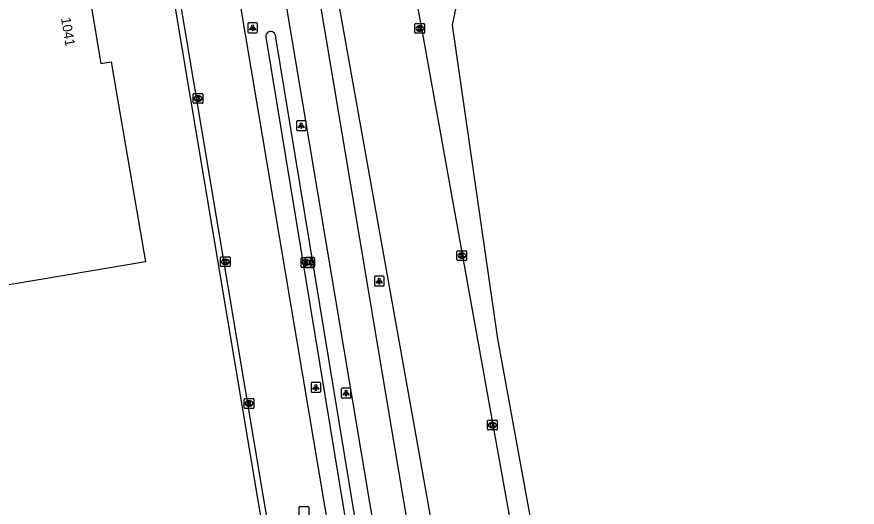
# Model space of a CAD drawing. Extents: x 154324 to 155743, y 382939 to 384183.
# Drawn here: x 155014.9 to 155101.4, y 383566.8 to 383617.3 of the extents above; entities that cross this region are included whole.
import ezdxf

# ---------------------------------------------------------------- set-up
doc = ezdxf.new("R2010")
doc.units = 0
for name, color, linetype in [('IMGEO_Brandkraan', 7, 'Continuous'), ('IMGEO_Fietspad_gesloten', 7, 'Continuous'), ('IMGEO_Greppel_droge_sloot', 7, 'Continuous'), ('IMGEO_Kolk', 7, 'Continuous'), ('IMGEO_Lichtpunt', 7, 'Continuous'), ('IMGEO_Loofbos', 7, 'Continuous'), ('IMGEO_Pand', 7, 'Continuous'), ('IMGEO_Pand_nummerreeks', 7, 'Continuous'), ('IMGEO_Rijbaan_lokaal_gesloten', 7, 'Continuous'), ('IMGEO_Rijbaan_lokaal_open', 7, 'Continuous'), ('IMGEO_Rijbaan_regionaal_gesloten', 7, 'Continuous'), ('IMGEO_Rioolput', 7, 'Continuous'), ('IMGEO_Verklikker', 7, 'Continuous')]:
    doc.layers.add(name, color=color, linetype=linetype)

msp = doc.modelspace()

# ---------------------------------------------------------------- linework, layer by layer
at = {"layer": 'IMGEO_Brandkraan'}
for p, q in [((155044.137, 383591.543), (155044.137, 383592.395)), ((155044.212, 383592.469), (155045.064, 383592.469)), ((155044.625, 383592.249), (155044.65, 383592.249)), ((155045.138, 383592.395), (155045.138, 383591.543)), ((155045.064, 383591.469), (155044.212, 383591.469)), ((155044.648, 383591.689), (155044.623, 383591.689))]:
    msp.add_line(p, q, dxfattribs=at)
for points in [[(155044.137, 383591.543), (155044.137, 383592.395)], [(155044.212, 383592.469), (155045.064, 383592.469)], [(155044.485, 383592.169), (155044.485, 383591.769), (155044.698, 383591.769)], [(155044.716, 383592.169), (155044.485, 383592.169)], [(155044.664, 383592.088), (155044.61, 383592.088), (155044.61, 383592.012)], [(155044.61, 383592.012), (155044.663, 383592.012)], [(155044.672, 383591.936), (155044.61, 383591.936), (155044.61, 383591.855)], [(155044.61, 383591.855), (155044.672, 383591.855)], [(155045.138, 383592.395), (155045.138, 383591.543)], [(155045.064, 383591.469), (155044.212, 383591.469)]]:
    msp.add_lwpolyline(points, dxfattribs=at)
for centre, radius, start, end in [((155044.214, 383592.393), 0.0765, 91.55205, 178.44795), ((155044.214, 383592.393), 0.0765, 91.55205, 178.44795), ((155044.665, 383592.05), 0.0379, 267.82845, 90.93552), ((155044.673, 383591.895), 0.0404, 269.87594, 90.50774), ((155044.704, 383592.02), 0.251, 268.66757, 293.53466), ((155044.72, 383592.024), 0.145, 59.4692, 91.53667), ((155044.745, 383592.071), 0.0922, 285.51372, 58.15012), ((155044.75, 383591.879), 0.105, 301.31148, 78.98903), ((155045.062, 383592.393), 0.0765, 1.55205, 88.44795), ((155045.062, 383592.393), 0.0765, 1.55205, 88.44795), ((155044.214, 383591.545), 0.0765, 181.55205, 268.44795), ((155044.214, 383591.545), 0.0765, 181.55205, 268.44795), ((155045.062, 383591.545), 0.0765, 271.55205, 358.44795), ((155045.062, 383591.545), 0.0765, 271.55205, 358.44795)]:
    msp.add_arc(centre, radius, start, end, dxfattribs=at)
for centre, major_axis, ratio, start_param, end_param in [((155044.624, 383591.969), (-0.387, 0.002), 0.722429, 4.712389, 7.853982), ((155044.649, 383591.969), (-0.39, 0.002), 0.717154, 1.570796, 4.712389)]:
    msp.add_ellipse(centre, major_axis=major_axis, ratio=ratio, start_param=start_param, end_param=end_param, dxfattribs=at)
at = {"layer": 'IMGEO_Fietspad_gesloten'}
for points in [[(155069.375, 383489.212), (155067.803, 383490.288), (155064.93, 383506.848), (155055.586, 383562.322), (155035.787, 383680.446), (155030.556, 383711.937), (155024.582, 383747.491), (155023.65, 383752.887)], [(155020.155, 383752.117), (155027.003, 383711.594), (155027.513, 383708.543), (155029.197, 383698.769), (155030.596, 383690.066), (155052.123, 383561.719), (155057.1, 383532.805), (155064.796, 383488.095)]]:
    msp.add_lwpolyline(points, dxfattribs=at)
at = {"layer": 'IMGEO_Greppel_droge_sloot'}
for points in [[(155040.514, 383615.174), (155060.78, 383492.297)], [(155061.766, 383492.46), (155041.5, 383615.337)]]:
    msp.add_lwpolyline(points, dxfattribs=at)
msp.add_arc((155041.007, 383615.256), 0.5, 9.30266, 189.47118, dxfattribs=at)
at = {"layer": 'IMGEO_Kolk'}
for p, q in [((155055.864, 383615.653), (155055.864, 383616.505)), ((155055.939, 383616.579), (155056.791, 383616.579)), ((155056.352, 383616.359), (155056.377, 383616.359)), ((155056.865, 383616.505), (155056.865, 383615.653)), ((155056.791, 383615.579), (155055.939, 383615.579)), ((155056.375, 383615.799), (155056.35, 383615.799)), ((155033.026, 383608.442), (155033.026, 383609.294)), ((155033.101, 383609.368), (155033.953, 383609.368)), ((155033.514, 383609.148), (155033.539, 383609.148)), ((155034.027, 383609.294), (155034.027, 383608.442)), ((155033.953, 383608.368), (155033.101, 383608.368)), ((155033.537, 383608.588), (155033.512, 383608.588)), ((155060.19, 383592.251), (155060.19, 383593.103)), ((155060.265, 383593.177), (155061.117, 383593.177)), ((155060.678, 383592.957), (155060.703, 383592.957)), ((155061.191, 383593.103), (155061.191, 383592.251)), ((155035.847, 383591.622), (155035.847, 383592.474)), ((155035.922, 383592.548), (155036.774, 383592.548)), ((155036.358, 383591.768), (155036.333, 383591.768)), ((155036.335, 383592.328), (155036.36, 383592.328)), ((155036.848, 383592.474), (155036.848, 383591.622)), ((155061.117, 383592.177), (155060.265, 383592.177)), ((155060.701, 383592.397), (155060.676, 383592.397)), ((155036.774, 383591.548), (155035.922, 383591.548)), ((155038.282, 383577.025), (155038.282, 383577.877)), ((155038.357, 383577.951), (155039.209, 383577.951)), ((155039.283, 383577.877), (155039.283, 383577.025)), ((155038.793, 383577.171), (155038.768, 383577.171)), ((155038.77, 383577.731), (155038.795, 383577.731)), ((155039.209, 383576.951), (155038.357, 383576.951)), ((155063.341, 383574.803), (155063.341, 383575.655)), ((155063.416, 383575.729), (155064.268, 383575.729)), ((155063.829, 383575.509), (155063.854, 383575.509)), ((155064.342, 383575.655), (155064.342, 383574.803)), ((155064.268, 383574.729), (155063.416, 383574.729)), ((155063.852, 383574.949), (155063.827, 383574.949))]:
    msp.add_line(p, q, dxfattribs=at)
for points in [[(155055.864, 383615.653), (155055.864, 383616.505)], [(155055.939, 383616.579), (155056.791, 383616.579)], [(155056.185, 383616.279), (155056.308, 383616.279), (155056.308, 383616.128), (155056.438, 383616.279), (155056.602, 383616.279), (155056.456, 383616.128), (155056.609, 383615.879), (155056.457, 383615.879), (155056.372, 383616.043), (155056.308, 383615.976), (155056.308, 383615.879), (155056.185, 383615.879), (155056.185, 383616.279)], [(155056.865, 383616.505), (155056.865, 383615.653)], [(155056.791, 383615.579), (155055.939, 383615.579)], [(155033.026, 383608.442), (155033.026, 383609.294)], [(155033.101, 383609.368), (155033.953, 383609.368)], [(155033.347, 383609.068), (155033.47, 383609.068), (155033.47, 383608.917), (155033.6, 383609.068), (155033.764, 383609.068), (155033.618, 383608.917), (155033.771, 383608.668), (155033.619, 383608.668), (155033.534, 383608.832), (155033.47, 383608.765), (155033.47, 383608.668), (155033.347, 383608.668), (155033.347, 383609.068)], [(155034.027, 383609.294), (155034.027, 383608.442)], [(155033.953, 383608.368), (155033.101, 383608.368)], [(155060.19, 383592.251), (155060.19, 383593.103)], [(155060.265, 383593.177), (155061.117, 383593.177)], [(155060.511, 383592.877), (155060.634, 383592.877), (155060.634, 383592.726), (155060.764, 383592.877), (155060.928, 383592.877), (155060.782, 383592.726), (155060.935, 383592.477), (155060.783, 383592.477), (155060.698, 383592.641), (155060.634, 383592.574), (155060.634, 383592.477), (155060.511, 383592.477), (155060.511, 383592.877)], [(155061.191, 383593.103), (155061.191, 383592.251)], [(155035.847, 383591.622), (155035.847, 383592.474)], [(155035.922, 383592.548), (155036.774, 383592.548)], [(155036.168, 383592.248), (155036.291, 383592.248), (155036.291, 383592.097), (155036.421, 383592.248), (155036.585, 383592.248), (155036.439, 383592.097), (155036.592, 383591.848), (155036.44, 383591.848), (155036.355, 383592.012), (155036.291, 383591.945), (155036.291, 383591.848), (155036.168, 383591.848), (155036.168, 383592.248)], [(155036.848, 383592.474), (155036.848, 383591.622)], [(155061.117, 383592.177), (155060.265, 383592.177)], [(155036.774, 383591.548), (155035.922, 383591.548)], [(155038.282, 383577.025), (155038.282, 383577.877)], [(155038.357, 383577.951), (155039.209, 383577.951)], [(155039.283, 383577.877), (155039.283, 383577.025)], [(155038.603, 383577.651), (155038.726, 383577.651), (155038.726, 383577.5), (155038.856, 383577.651), (155039.02, 383577.651), (155038.874, 383577.5), (155039.027, 383577.251), (155038.875, 383577.251), (155038.79, 383577.415), (155038.726, 383577.348), (155038.726, 383577.251), (155038.603, 383577.251), (155038.603, 383577.651)], [(155039.209, 383576.951), (155038.357, 383576.951)], [(155063.341, 383574.803), (155063.341, 383575.655)], [(155063.416, 383575.729), (155064.268, 383575.729)], [(155063.662, 383575.429), (155063.785, 383575.429), (155063.785, 383575.278), (155063.915, 383575.429), (155064.079, 383575.429), (155063.933, 383575.278), (155064.086, 383575.029), (155063.934, 383575.029), (155063.849, 383575.193), (155063.785, 383575.126), (155063.785, 383575.029), (155063.662, 383575.029), (155063.662, 383575.429)], [(155064.342, 383575.655), (155064.342, 383574.803)], [(155064.268, 383574.729), (155063.416, 383574.729)]]:
    msp.add_lwpolyline(points, dxfattribs=at)
for centre, start, end in [((155055.941, 383616.503), 91.55205, 178.44795), ((155055.941, 383616.503), 91.55205, 178.44795), ((155056.789, 383616.503), 1.55205, 88.44795), ((155056.789, 383616.503), 1.55205, 88.44795), ((155055.941, 383615.655), 181.55205, 268.44795), ((155055.941, 383615.655), 181.55205, 268.44795), ((155056.789, 383615.655), 271.55205, 358.44795), ((155056.789, 383615.655), 271.55205, 358.44795), ((155033.103, 383609.292), 91.55205, 178.44795), ((155033.103, 383609.292), 91.55205, 178.44795), ((155033.951, 383609.292), 1.55205, 88.44795), ((155033.951, 383609.292), 1.55205, 88.44795), ((155033.103, 383608.444), 181.55205, 268.44795), ((155033.103, 383608.444), 181.55205, 268.44795), ((155033.951, 383608.444), 271.55205, 358.44795), ((155033.951, 383608.444), 271.55205, 358.44795), ((155060.267, 383593.101), 91.55205, 178.44795), ((155060.267, 383593.101), 91.55205, 178.44795), ((155061.115, 383593.101), 1.55205, 88.44795), ((155061.115, 383593.101), 1.55205, 88.44795), ((155035.924, 383592.472), 91.55205, 178.44795), ((155035.924, 383592.472), 91.55205, 178.44795), ((155036.772, 383592.472), 1.55205, 88.44795), ((155036.772, 383592.472), 1.55205, 88.44795), ((155060.267, 383592.253), 181.55205, 268.44795), ((155060.267, 383592.253), 181.55205, 268.44795), ((155061.115, 383592.253), 271.55205, 358.44795), ((155061.115, 383592.253), 271.55205, 358.44795), ((155035.924, 383591.624), 181.55205, 268.44795), ((155035.924, 383591.624), 181.55205, 268.44795), ((155036.772, 383591.624), 271.55205, 358.44795), ((155036.772, 383591.624), 271.55205, 358.44795), ((155038.359, 383577.875), 91.55205, 178.44795), ((155038.359, 383577.875), 91.55205, 178.44795), ((155039.207, 383577.875), 1.55205, 88.44795), ((155039.207, 383577.875), 1.55205, 88.44795), ((155038.359, 383577.027), 181.55205, 268.44795), ((155038.359, 383577.027), 181.55205, 268.44795), ((155039.207, 383577.027), 271.55205, 358.44795), ((155039.207, 383577.027), 271.55205, 358.44795), ((155063.418, 383575.653), 91.55205, 178.44795), ((155063.418, 383575.653), 91.55205, 178.44795), ((155064.266, 383575.653), 1.55205, 88.44795), ((155064.266, 383575.653), 1.55205, 88.44795), ((155063.418, 383574.805), 181.55205, 268.44795), ((155063.418, 383574.805), 181.55205, 268.44795), ((155064.266, 383574.805), 271.55205, 358.44795), ((155064.266, 383574.805), 271.55205, 358.44795)]:
    msp.add_arc(centre, 0.0765, start, end, dxfattribs=at)
for centre, major_axis, ratio, start_param, end_param in [((155056.351, 383616.079), (-0.387, 0.002), 0.722429, 4.712389, 7.853982), ((155056.376, 383616.079), (-0.39, 0.002), 0.717154, 1.570796, 4.712389), ((155033.513, 383608.868), (-0.387, 0.002), 0.722429, 4.712389, 7.853982), ((155033.538, 383608.868), (-0.39, 0.002), 0.717154, 1.570796, 4.712389), ((155060.677, 383592.677), (-0.387, 0.002), 0.722429, 4.712389, 7.853982), ((155060.702, 383592.677), (-0.39, 0.002), 0.717154, 1.570796, 4.712389), ((155036.334, 383592.048), (-0.387, 0.002), 0.722429, 4.712389, 7.853982), ((155036.359, 383592.048), (-0.39, 0.002), 0.717154, 1.570796, 4.712389), ((155038.769, 383577.451), (-0.387, 0.002), 0.722429, 4.712389, 7.853982), ((155038.794, 383577.451), (-0.39, 0.002), 0.717154, 1.570796, 4.712389), ((155063.828, 383575.229), (-0.387, 0.002), 0.722429, 4.712389, 7.853982), ((155063.853, 383575.229), (-0.39, 0.002), 0.717154, 1.570796, 4.712389)]:
    msp.add_ellipse(centre, major_axis=major_axis, ratio=ratio, start_param=start_param, end_param=end_param, dxfattribs=at)
at = {"layer": 'IMGEO_Lichtpunt'}
for p, q in [((155038.654, 383616.54), (155038.654, 383615.733)), ((155038.654, 383616.54), (155038.654, 383615.733)), ((155039.556, 383616.635), (155038.748, 383616.635)), ((155039.556, 383616.635), (155038.748, 383616.635)), ((155039.65, 383615.733), (155039.65, 383616.54)), ((155039.65, 383615.733), (155039.65, 383616.54)), ((155038.748, 383615.639), (155039.556, 383615.639)), ((155038.748, 383615.639), (155039.556, 383615.639)), ((155043.658, 383606.464), (155043.658, 383605.657)), ((155043.658, 383606.464), (155043.658, 383605.657)), ((155044.56, 383606.559), (155043.752, 383606.559)), ((155044.56, 383606.559), (155043.752, 383606.559)), ((155044.654, 383605.657), (155044.654, 383606.464)), ((155044.654, 383605.657), (155044.654, 383606.464)), ((155043.752, 383605.563), (155044.56, 383605.563)), ((155043.752, 383605.563), (155044.56, 383605.563)), ((155051.687, 383590.453), (155051.687, 383589.646)), ((155051.687, 383590.453), (155051.687, 383589.646)), ((155052.589, 383590.548), (155051.781, 383590.548)), ((155052.589, 383590.548), (155051.781, 383590.548)), ((155052.683, 383589.646), (155052.683, 383590.453)), ((155052.683, 383589.646), (155052.683, 383590.453)), ((155051.781, 383589.552), (155052.589, 383589.552)), ((155051.781, 383589.552), (155052.589, 383589.552)), ((155046.065, 383579.607), (155045.257, 383579.607)), ((155046.065, 383579.607), (155045.257, 383579.607)), ((155045.163, 383579.512), (155045.163, 383578.705)), ((155045.163, 383579.512), (155045.163, 383578.705)), ((155046.159, 383578.705), (155046.159, 383579.512)), ((155046.159, 383578.705), (155046.159, 383579.512)), ((155048.269, 383578.922), (155048.269, 383578.115)), ((155048.269, 383578.922), (155048.269, 383578.115)), ((155049.171, 383579.017), (155048.363, 383579.017)), ((155049.171, 383579.017), (155048.363, 383579.017)), ((155049.265, 383578.115), (155049.265, 383578.922)), ((155049.265, 383578.115), (155049.265, 383578.922)), ((155045.257, 383578.611), (155046.065, 383578.611)), ((155045.257, 383578.611), (155046.065, 383578.611)), ((155048.363, 383578.021), (155049.171, 383578.021)), ((155048.363, 383578.021), (155049.171, 383578.021))]:
    msp.add_line(p, q, dxfattribs=at)
for points in [[(155039.028, 383616.204), (155039.067, 383616.176), (155038.879, 383615.914), (155038.841, 383615.941), (155039.028, 383616.204)], [(155039.13, 383616.156), (155039.177, 383616.156), (155039.177, 383615.834), (155039.13, 383615.834), (155039.13, 383616.156)], [(155039.24, 383616.176), (155039.278, 383616.203), (155039.465, 383615.941), (155039.426, 383615.913), (155039.24, 383616.176)], [(155044.032, 383606.128), (155044.071, 383606.1), (155043.883, 383605.838), (155043.845, 383605.865), (155044.032, 383606.128)], [(155044.134, 383606.08), (155044.181, 383606.08), (155044.181, 383605.758), (155044.134, 383605.758), (155044.134, 383606.08)], [(155044.244, 383606.1), (155044.282, 383606.127), (155044.469, 383605.865), (155044.43, 383605.837), (155044.244, 383606.1)], [(155052.061, 383590.117), (155052.1, 383590.089), (155051.912, 383589.827), (155051.874, 383589.854), (155052.061, 383590.117)], [(155052.163, 383590.069), (155052.21, 383590.069), (155052.21, 383589.747), (155052.163, 383589.747), (155052.163, 383590.069)], [(155052.273, 383590.089), (155052.311, 383590.116), (155052.498, 383589.854), (155052.459, 383589.826), (155052.273, 383590.089)], [(155045.537, 383579.176), (155045.576, 383579.148), (155045.388, 383578.886), (155045.35, 383578.913), (155045.537, 383579.176)], [(155045.639, 383579.128), (155045.686, 383579.128), (155045.686, 383578.806), (155045.639, 383578.806), (155045.639, 383579.128)], [(155045.749, 383579.148), (155045.787, 383579.175), (155045.974, 383578.913), (155045.935, 383578.885), (155045.749, 383579.148)], [(155048.643, 383578.586), (155048.682, 383578.558), (155048.494, 383578.296), (155048.456, 383578.323), (155048.643, 383578.586)], [(155048.745, 383578.538), (155048.792, 383578.538), (155048.792, 383578.216), (155048.745, 383578.216), (155048.745, 383578.538)], [(155048.855, 383578.558), (155048.893, 383578.585), (155049.08, 383578.323), (155049.041, 383578.295), (155048.855, 383578.558)]]:
    msp.add_lwpolyline(points, dxfattribs=at)
for centre in [(155039.153, 383616.338), (155044.157, 383606.262), (155052.186, 383590.251), (155045.662, 383579.31), (155048.768, 383578.72)]:
    msp.add_circle(centre, 0.0994, dxfattribs=at)
for centre, start, end in [((155038.748, 383616.54), 90, 180), ((155038.748, 383616.54), 90, 180), ((155039.556, 383616.54), 0, 90), ((155039.556, 383616.54), 0, 90), ((155038.748, 383615.733), 180, 270), ((155038.748, 383615.733), 180, 270), ((155039.556, 383615.733), 270, 0), ((155039.556, 383615.733), 270, 360), ((155043.752, 383606.464), 90, 180), ((155043.752, 383606.464), 90, 180), ((155044.56, 383606.464), 0, 90), ((155044.56, 383606.464), 0, 90), ((155043.752, 383605.657), 180, 270), ((155043.752, 383605.657), 180, 270), ((155044.56, 383605.657), 270, 0), ((155044.56, 383605.657), 270, 360), ((155051.781, 383590.453), 90, 180), ((155051.781, 383590.453), 90, 180), ((155052.589, 383590.453), 0, 90), ((155052.589, 383590.453), 0, 90), ((155051.781, 383589.646), 180, 270), ((155051.781, 383589.646), 180, 270), ((155052.589, 383589.646), 270, 0), ((155052.589, 383589.646), 270, 360), ((155045.257, 383579.512), 90, 180), ((155045.257, 383579.512), 90, 180), ((155046.065, 383579.512), 0, 90), ((155046.065, 383579.512), 0, 90), ((155048.363, 383578.922), 90, 180), ((155048.363, 383578.922), 90, 180), ((155049.171, 383578.922), 0, 90), ((155049.171, 383578.922), 0, 90), ((155045.257, 383578.705), 180, 270), ((155045.257, 383578.705), 180, 270), ((155046.065, 383578.705), 270, 0), ((155046.065, 383578.705), 270, 360), ((155048.363, 383578.115), 180, 270), ((155048.363, 383578.115), 180, 270), ((155049.171, 383578.115), 270, 0), ((155049.171, 383578.115), 270, 360)]:
    msp.add_arc(centre, 0.0946, start, end, dxfattribs=at)
at = {"layer": 'IMGEO_Loofbos'}
msp.add_lwpolyline([(155150.12, 383546.849), (155147.672, 383535.525), (155141.293, 383537.615), (155133.684, 383529.375), (155124.807, 383520.48), (155115.997, 383521.813), (155107.115, 383520.76), (155104.634, 383525.749), (155106.245, 383533.735), (155095.073, 383538.97), (155091.938, 383544.397), (155085.842, 383544.943), (155077.749, 383551.031), (155073.706, 383549.691), (155069.247, 383557.613), (155064.414, 383584.109), (155059.736, 383616.398), (155060.565, 383620.426)], dxfattribs=at)
at = {"layer": 'IMGEO_Pand'}
msp.add_lwpolyline([(154968.856, 383582.036), (154965.968, 383599.167), (154982.677, 383602.011), (154981.855, 383606.811), (154988.34, 383607.922), (154989.336, 383602.109), (154998.998, 383603.747), (154995.748, 383622.105), (154986.045, 383620.456), (154986.86, 383615.621), (154980.368, 383614.527), (154979.569, 383619.356), (154962.835, 383616.513), (154959.94, 383633.571), (155019.3, 383643.685), (155023.472, 383619.228), (155022.401, 383619.041), (155023.514, 383612.464), (155024.589, 383612.647), (155025.346, 383608.213), (155028.11, 383592.025), (154968.856, 383582.036)], dxfattribs=at)
at = {"layer": 'IMGEO_Rijbaan_lokaal_gesloten'}
for points in [[(155059.928, 383487.45), (155052.477, 383531.831), (155025.49, 383692.18), (155022.669, 383708.88), (155021.296, 383718.742)], [(155059.439, 383453.463), (155046.503, 383530.572), (155016.871, 383707.197)]]:
    msp.add_lwpolyline(points, dxfattribs=at)
at = {"layer": 'IMGEO_Rijbaan_lokaal_open'}
msp.add_lwpolyline([(155065.709, 383396.485), (155065.341, 383401.33), (155064.659, 383408.986), (155063.139, 383423.564), (155063.03, 383424.403), (155061.613, 383435.27), (155060.487, 383443.041), (155058.846, 383453.397), (155045.918, 383530.449), (155024.164, 383660.104), (155016.277, 383707.107)], dxfattribs=at)
at = {"layer": 'IMGEO_Rijbaan_regionaal_gesloten'}
for points in [[(155023.592, 383759.163), (155025.319, 383747.582), (155031.523, 383712.699), (155040.998, 383657.511), (155047.66, 383620.638), (155058.726, 383558.566), (155063.68, 383530.41), (155070.593, 383489.047)], [(155030.993, 383757.82), (155045.927, 383675.069), (155050.278, 383650.736), (155055.096, 383623.794), (155056.54, 383616.113), (155069.465, 383544.367)]]:
    msp.add_lwpolyline(points, dxfattribs=at)
at = {"layer": 'IMGEO_Rioolput'}
for p, q in [((155043.926, 383565.921), (155043.926, 383566.773)), ((155044.001, 383566.847), (155044.853, 383566.847)), ((155044.927, 383566.773), (155044.927, 383565.921))]:
    msp.add_line(p, q, dxfattribs=at)
for points in [[(155043.926, 383565.921), (155043.926, 383566.773)], [(155044.001, 383566.847), (155044.853, 383566.847)], [(155044.927, 383566.773), (155044.927, 383565.921)]]:
    msp.add_lwpolyline(points, dxfattribs=at)
for centre, start, end in [((155044.003, 383566.771), 91.55205, 178.44795), ((155044.003, 383566.771), 91.55205, 178.44795), ((155044.851, 383566.771), 1.55205, 88.44795), ((155044.851, 383566.771), 1.55205, 88.44795)]:
    msp.add_arc(centre, 0.0765, start, end, dxfattribs=at)
at = {"layer": 'IMGEO_Verklikker'}
for p, q in [((155044.547, 383591.572), (155044.547, 383592.372)), ((155044.547, 383592.372), (155044.547, 383591.572)), ((155044.647, 383592.472), (155045.437, 383592.472)), ((155045.437, 383592.472), (155044.647, 383592.472)), ((155045.537, 383592.372), (155045.537, 383591.572)), ((155045.537, 383591.572), (155045.537, 383592.372)), ((155045.437, 383591.472), (155044.647, 383591.472)), ((155044.647, 383591.472), (155045.437, 383591.472))]:
    msp.add_line(p, q, dxfattribs=at)
for points in [[(155044.648, 383592.204), (155045.436, 383592.204), (155045.436, 383591.74), (155044.648, 383591.74), (155044.648, 383592.204)], [(155044.713, 383592.139), (155044.713, 383591.805), (155045.371, 383591.805), (155045.371, 383592.139), (155044.713, 383592.139)]]:
    msp.add_lwpolyline(points, dxfattribs=at)
for centre, start, end in [((155044.647, 383592.372), 90, 180), ((155044.647, 383592.372), 90, 180), ((155045.437, 383592.372), 0, 90), ((155045.437, 383592.372), 360, 90), ((155044.647, 383591.572), 180, 270), ((155044.647, 383591.572), 180, 270), ((155045.437, 383591.572), 270, 0), ((155045.437, 383591.572), 270, 0)]:
    msp.add_arc(centre, 0.1, start, end, dxfattribs=at)

# ---------------------------------------------------------------- texts
at = {"layer": 'IMGEO_Pand_nummerreeks'}
msp.add_text('1041', height=1, rotation=279.53381, dxfattribs=at).set_placement((155019.405, 383617.121))

doc.saveas('drawing.dxf')
